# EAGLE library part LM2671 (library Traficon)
SIMPLE SWITCHER Power Converter High Efficiency 500mA Step-Down Voltage Regulator with Features
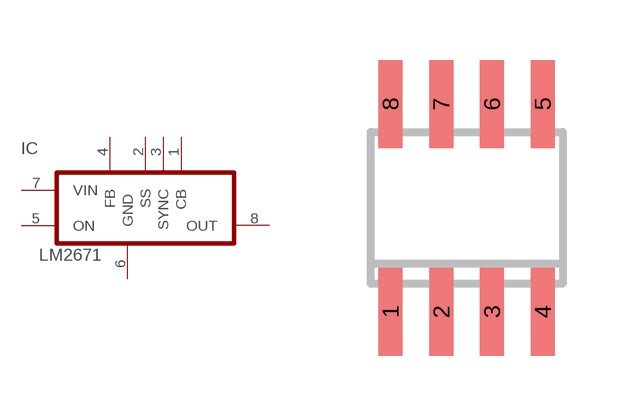
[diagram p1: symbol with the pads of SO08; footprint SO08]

Designator prefix IC

## LM2671-ADJ  [SO08]
1  CB  pas
2  SS  pas
3  SYNC  pas
4  FB  pas
5  ON  pas
6  GND  pas
7  VIN  pas
8  OUT  pas

## LM2671-3.3  [SO08]
Pads as for SO08

## Footprint SO08 (pad centres in mm)
Small Outline Package
smd 0.6 x 2.2: 1 -1.905,-2.6; 2 -0.635,-2.6; 3 0.635,-2.6; 4 1.905,-2.6; 5 1.905,2.6; 6 0.635,2.6; 7 -0.635,2.6; 8 -1.905,2.6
